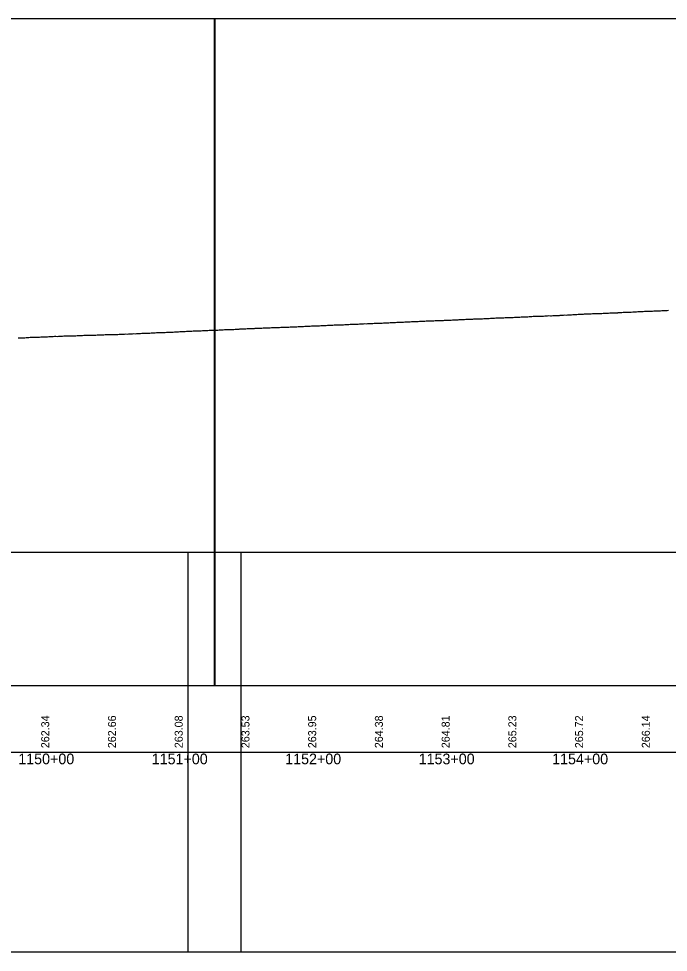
# Model space of a CAD drawing. Extents: x -3627 to 47473, y 2850 to 4350.
# Drawn here: x 2353 to 2840, y 2850 to 3550 of the extents above; entities that cross this region are included whole.
import ezdxf

# ---------------------------------------------------------------- set-up
doc = ezdxf.new("R2010")
doc.units = 0
for name, color, linetype in [('RD_DDB_Profile_EX', 7, 'Continuous'), ('RD_DDB_StaTX', 7, 'Continuous'), ('RD_DDB_StripGrade', 7, 'Continuous'), ('RD_GPK_Profile_Cell', 7, 'Continuous'), ('RD_SHT_ShtClip', 7, 'Continuous')]:
    doc.layers.add(name, color=color, linetype=linetype)

msp = doc.modelspace()

# ---------------------------------------------------------------- linework, layer by layer
at = {"layer": 'RD_DDB_Profile_EX'}
for points in [[(2633.790512, 3322.19143), (2634.793916, 3322.19946), (2635.790637, 3322.29861), (2636.793829, 3322.34696), (2637.783841, 3322.395415), (2638.787037, 3322.49412), (2639.124858, 3322.512035), (2639.79033, 3322.54469), (2640.787584, 3322.505735), (2641.790926, 3322.508085), (2642.788456, 3322.60648), (2643.791934, 3322.60825), (2644.781844, 3322.66005), (2645.785627, 3322.71375), (2646.394238, 3322.77472), (2646.782753, 3322.81139), (2647.78638, 3322.86255), (2648.790306, 3322.86363), (2650.028928, 3322.983285), (2650.791259, 3323.055685), (2651.781736, 3323.056225), (2652.785513, 3323.060725), (2653.782887, 3323.111245), (2654.787109, 3323.2091), (2655.78656, 3323.15732), (2656.750391, 3323.20531), (2657.298309, 3323.26141), (2657.787457, 3323.309415), (2658.785119, 3323.354915), (2659.78944, 3323.402415), (2660.932999, 3323.39969), (2661.749978, 3323.40096), (2662.537004, 3323.453005), (2663.541312, 3323.45581), (2664.567689, 3323.507625), (2665.528994, 3323.60698), (2666.53333, 3323.60918), (2667.530566, 3323.70545), (2668.534916, 3323.65942), (2669.532193, 3323.661045), (2670.529467, 3323.806715), (2671.533843, 3323.808315), (2671.837069, 3323.823375), (2672.53115, 3323.85755), (2673.535298, 3323.95841), (2674.532888, 3323.961215), (2675.530485, 3324.010165), (2676.534404, 3324.0585), (2677.532046, 3324.056825), (2678.536236, 3324.10506), (2679.106449, 3324.161215), (2679.533624, 3324.201185), (2680.531326, 3324.200825), (2681.535561, 3324.19834), (2682.741139, 3324.30623), (2683.537545, 3324.34514), (2684.535018, 3324.437805), (2685.532795, 3324.48469), (2686.537385, 3324.485665), (2687.534615, 3324.531935), (2688.539255, 3324.62796), (2689.536789, 3324.67408), (2690.010519, 3324.67224), (2690.534361, 3324.672385), (2691.539068, 3324.719975), (2692.536669, 3324.763055), (2693.645209, 3324.77055), (2694.539044, 3324.855675), (2695.536715, 3324.90045), (2696.561209, 3324.9003), (2697.559781, 3324.98992), (2698.564217, 3325.033595), (2699.562895, 3325.027935), (2700.503658, 3325.022265), (2700.948067, 3325.03156), (2701.939405, 3325.132825), (2702.944497, 3325.23141), (2703.949212, 3325.233025), (2704.549279, 3325.20557), (2704.940935, 3325.19241), (2705.945371, 3325.20102), (2706.937117, 3325.349485), (2708.183969, 3325.40145), (2708.946822, 3325.405865), (2709.938619, 3325.503985), (2710.943539, 3325.604555), (2711.935321, 3325.609905), (2712.940008, 3325.61436), (2713.938649, 3325.666495), (2714.936878, 3325.716635), (2715.45335, 3325.74353), (2715.941954, 3325.768325), (2716.933874, 3325.817755), (2717.939007, 3325.8671), (2719.08804, 3325.870875), (2719.935826, 3325.871815), (2720.941373, 3325.924695), (2721.933068, 3325.97144), (2722.938637, 3326.02415), (2723.937248, 3326.07643), (2724.935785, 3326.12437)], [(2724.935785, 3326.12437), (2725.941438, 3326.17435), (2726.35742, 3326.15356), (2726.932996, 3326.128455), (2727.938762, 3326.17986), (2728.937489, 3326.327285), (2729.99211, 3326.374975), (2730.94201, 3326.42285), (2731.934044, 3326.46953), (2732.93993, 3326.46801), (2733.911784, 3326.4693), (2734.917295, 3326.567595), (2735.923136, 3326.66145), (2736.914845, 3326.66012), (2737.26149, 3326.69387), (2737.920377, 3326.755585), (2738.912475, 3326.85127), (2739.918018, 3326.85112), (2740.923555, 3326.84862), (2741.915716, 3326.893505), (2742.739913, 3326.89674), (2743.739141, 3326.903055), (2744.739051, 3326.956795), (2745.73869, 3327.009845), (2746.744588, 3327.06056), (2747.74456, 3327.159265), (2748.16556, 3327.15962), (2748.737001, 3327.15988), (2749.736737, 3327.260045), (2750.736786, 3327.36037), (2751.80025, 3327.31729), (2752.736051, 3327.32088), (2753.735899, 3327.370565), (2754.735732, 3327.42215), (2755.735312, 3327.471565), (2756.735545, 3327.52249), (2757.735101, 3327.56859), (2758.734749, 3327.57368), (2759.06963, 3327.5907), (2759.735056, 3327.624085), (2760.734813, 3327.720125), (2761.734854, 3327.816055), (2762.735199, 3327.864125), (2763.735066, 3327.81766), (2764.735218, 3327.86903), (2765.735386, 3327.96228), (2766.33901, 3327.990815), (2766.729231, 3328.011325), (2767.736115, 3328.05961), (2768.736404, 3328.10617), (2769.973701, 3328.176045), (2770.736773, 3328.24652), (2771.737183, 3328.296645), (2772.737594, 3328.34456), (2773.738021, 3328.394665), (2774.738559, 3328.44183), (2775.732168, 3328.532085), (2776.684649, 3328.57671), (2777.368549, 3328.58376), (2778.369765, 3328.63029), (2779.364795, 3328.636535), (2780.373275, 3328.687745), (2780.877771, 3328.740535), (2781.368307, 3328.78908), (2782.363056, 3328.79676), (2783.371576, 3328.895115), (2784.512461, 3328.9432), (2785.367865, 3328.902265), (2786.370208, 3328.906845), (2787.364985, 3328.963385), (2788.366255, 3329.01282), (2789.368632, 3329.0645), (2790.369926, 3329.06533), (2791.364997, 3329.16682), (2791.781841, 3329.21003), (2792.367135, 3329.26622), (2793.368465, 3329.264195), (2794.363568, 3329.314915), (2795.416531, 3329.319395), (2796.367351, 3329.36708), (2797.362495, 3329.465005), (2798.37092, 3329.468515), (2799.366079, 3329.470175), (2800.367498, 3329.51256), (2801.362695, 3329.513715), (2802.365193, 3329.567065), (2802.685911, 3329.597955), (2803.366382, 3329.66102), (2804.361636, 3329.661435), (2805.3704, 3329.75503), (2806.365661, 3329.85115), (2807.360983, 3329.898615), (2808.36951, 3329.897865), (2809.364835, 3329.89758), (2809.955291, 3329.95347), (2810.36639, 3329.99205), (2811.369052, 3330.04324), (2812.364455, 3330.04232), (2813.589981, 3330.174735), (2814.375418, 3330.323265), (2815.377009, 3330.319135)], [(2815.377009, 3330.319135), (2816.372724, 3330.31548), (2817.375286, 3330.364065), (2818.376953, 3330.40676), (2819.372783, 3330.44968), (2820.381987, 3330.44738), (2820.859361, 3330.493035), (2821.377107, 3330.542605), (2822.373061, 3330.63178), (2823.229437, 3330.637815), (2824.494051, 3330.656145), (2825.230309, 3330.693765), (2826.227656, 3330.700155), (2827.23172, 3330.703885), (2828.229476, 3330.76019), (2829.226609, 3330.910545), (2830.230809, 3330.913385), (2831.228678, 3330.916315), (2831.763432, 3330.94477), (2832.226226, 3330.966225), (2833.230227, 3331.06326), (2834.221138, 3331.06584), (2835.398122, 3331.17672), (2836.223222, 3331.2192), (2837.221029, 3331.22322), (2838.218797, 3331.179465), (2839.223316, 3331.22548), (2840.221611, 3331.36848)], [(2451.684694, 3314.29795), (2452.681468, 3314.34704), (2453.755665, 3314.40245), (2454.672582, 3314.44725), (2455.675191, 3314.547285), (2456.67779, 3314.597385), (2457.674714, 3314.64586), (2458.675539, 3314.695455), (2459.180865, 3314.745955), (2460.183572, 3314.79573), (2461.178315, 3314.79662), (2462.179176, 3314.79853), (2463.181943, 3314.79781), (2464.176745, 3314.898195), (2464.659735, 3314.923285), (2465.177642, 3314.949965), (2466.180482, 3315.048785), (2467.476991, 3315.085265), (2468.294425, 3315.043655), (2469.17921, 3314.99894), (2470.180222, 3315.19998), (2471.183143, 3315.198335), (2472.17812, 3315.247845), (2473.179224, 3315.29857), (2474.182225, 3315.346485), (2475.177279, 3315.395665), (2475.563805, 3315.395945), (2476.178422, 3315.3962), (2477.181518, 3315.393855), (2478.176648, 3315.492185), (2479.198495, 3315.640985), (2480.181026, 3315.63946), (2481.182316, 3315.58972), (2482.18551, 3315.686535), (2482.833185, 3315.717975), (2483.180769, 3315.735005), (2484.182164, 3315.883435), (2485.185445, 3315.880695), (2486.467876, 3315.85793), (2487.182242, 3315.92809), (2488.185643, 3315.97378), (2489.181073, 3315.971215), (2490.190464, 3316.0682), (2491.186079, 3316.115155), (2492.175247, 3316.162135), (2493.184193, 3316.209385), (2493.737256, 3316.26327), (2494.179308, 3316.30446), (2495.174456, 3316.301855), (2496.183562, 3316.34759), (2497.371946, 3316.392595), (2498.179977, 3316.39171), (2499.182757, 3316.485195), (2500.177979, 3316.53117), (2501.006636, 3316.534105), (2501.721192, 3316.5354), (2502.721232, 3316.5367), (2503.721273, 3316.58673), (2504.721324, 3316.6842), (2505.7215, 3316.781225), (2506.719763, 3316.83378), (2507.71979, 3316.88453), (2508.276016, 3316.88429), (2508.720028, 3316.885135), (2509.720546, 3316.88548), (2510.720864, 3316.93461), (2511.910706, 3317.0027), (2512.727499, 3317.08143), (2513.720169, 3317.082715), (2514.720635, 3317.082685), (2515.721127, 3317.178585), (2516.721744, 3317.27674), (2517.72219, 3317.273425), (2518.722803, 3317.32154), (2519.180086, 3317.34415), (2519.729364, 3317.370995), (2520.722365, 3317.37003), (2521.723135, 3317.41919), (2522.814776, 3317.475665), (2523.725081, 3317.560825), (2524.72602, 3317.60792), (2525.732789, 3317.610035), (2526.733769, 3317.607105), (2527.726931, 3317.70157), (2528.728031, 3317.74632), (2529.729132, 3317.79477), (2530.084156, 3317.8113), (2530.730344, 3317.843035), (2531.731615, 3317.887165), (2532.727277, 3317.887215), (2533.728085, 3317.88353), (2534.721429, 3317.9287), (2535.722287, 3318.022345), (2536.723505, 3318.11579), (2537.353536, 3318.112955), (2537.724101, 3318.113765), (2538.731359, 3318.113185), (2539.93407, 3318.15564), (2540.988226, 3318.1662), (2541.936477, 3318.259605), (2542.934592, 3318.35792)], [(2542.934592, 3318.35792), (2543.938671, 3318.360525), (2544.929381, 3318.41041), (2545.9279, 3318.41562), (2546.931784, 3318.46525), (2547.930297, 3318.51566), (2548.257607, 3318.51582), (2548.928515, 3318.51816), (2549.933176, 3318.61501), (2550.931133, 3318.66491), (2551.935444, 3318.714225), (2552.934165, 3318.763605), (2553.93253, 3318.81306), (2554.937303, 3318.81643), (2555.526987, 3318.816115), (2555.935422, 3318.815605), (2556.934262, 3318.871485), (2557.931403, 3318.9189), (2559.161677, 3318.97691), (2559.928526, 3319.01394), (2560.933176, 3319.014025), (2561.932144, 3319.01475), (2562.930766, 3319.115535), (2563.935909, 3319.11504), (2564.934332, 3319.210485), (2565.93306, 3319.258425), (2566.431057, 3319.28303), (2566.938271, 3319.30516), (2567.937131, 3319.35254), (2568.936065, 3319.39975), (2570.065747, 3319.413855), (2570.932981, 3319.49188), (2571.931989, 3319.538625), (2572.937414, 3319.59242), (2573.910466, 3319.63673), (2574.908926, 3319.68339), (2575.914055, 3319.728775), (2576.91251, 3319.77249), (2577.335127, 3319.77087), (2577.911389, 3319.76887), (2578.916131, 3319.819635), (2579.914635, 3319.862705), (2580.969817, 3319.962785), (2581.744461, 3320.058355), (2582.741745, 3320.01343), (2583.744685, 3320.06121), (2584.741517, 3320.11329), (2585.738822, 3320.120875), (2586.741882, 3320.126995), (2587.738804, 3320.175665), (2588.239197, 3320.251735), (2588.736211, 3320.321175), (2589.740778, 3320.37067), (2590.743959, 3320.37626), (2591.873887, 3320.43021), (2592.738117, 3320.43062), (2593.741783, 3320.480135), (2594.738926, 3320.480615), (2595.73651, 3320.53088), (2596.733772, 3320.53354), (2597.7372, 3320.632455), (2598.742002, 3320.772665), (2599.143268, 3320.7324), (2599.739336, 3320.68319), (2600.73672, 3320.72984), (2601.740687, 3320.87538), (2602.777958, 3320.883505), (2603.735937, 3321.02091), (2604.739614, 3321.02148), (2605.737126, 3321.023025), (2606.735044, 3321.024525), (2607.732692, 3321.069975), (2608.744097, 3321.120995), (2609.741741, 3321.169255), (2610.047338, 3321.16872), (2610.73986, 3321.170135), (2611.743789, 3321.266655), (2612.741571, 3321.35846), (2613.739361, 3321.312025), (2614.726502, 3321.359465), (2615.730387, 3321.44965), (2616.728036, 3321.49713), (2617.316718, 3321.4943), (2617.733226, 3321.492525), (2618.737201, 3321.544385), (2619.734948, 3321.588155), (2620.951408, 3321.597845), (2621.806675, 3321.60518), (2622.803027, 3321.65844), (2623.806501, 3321.75759), (2624.795838, 3321.76259), (2625.798595, 3321.819925), (2626.795455, 3321.875305), (2627.798226, 3321.8824), (2628.220788, 3321.925935), (2628.795135, 3321.97678), (2629.798034, 3322.03078), (2630.800949, 3322.03478), (2631.855478, 3322.092965), (2632.793828, 3322.18977), (2633.790512, 3322.19143)], [(2352.929829, 3310.73245), (2353.932394, 3310.733485), (2354.927051, 3310.83385), (2355.929615, 3310.83485), (2356.926078, 3310.834785), (2357.928642, 3310.835755), (2358.931152, 3310.93579), (2359.925859, 3310.93712), (2360.928376, 3310.98723), (2361.930941, 3311.087755), (2362.927403, 3311.087605), (2363.922099, 3311.088935), (2364.924622, 3311.139435), (2365.927187, 3311.14026), (2366.929763, 3311.19074), (2367.932327, 3311.240955), (2368.920908, 3311.29125), (2369.923469, 3311.44099), (2370.926002, 3311.49106), (2371.928565, 3311.442325), (2372.933068, 3311.44308), (2373.927318, 3311.494295), (2374.923934, 3311.54355), (2375.92635, 3311.59411), (2376.928766, 3311.644665), (2377.923035, 3311.74602), (2379.17513, 3311.79553), (2380.177626, 3311.845865), (2381.174174, 3311.84513), (2382.176655, 3311.795955), (2383.173183, 3311.84524), (2384.175679, 3311.89572), (2385.172227, 3311.945225), (2386.174722, 3311.995815), (2387.171272, 3312.094825), (2388.173733, 3312.09546), (2389.17028, 3312.095065), (2390.172776, 3312.19544), (2391.169325, 3312.24479), (2392.171819, 3312.245655), (2393.168349, 3312.1953), (2394.170829, 3312.24587), (2395.167378, 3312.29502), (2396.169872, 3312.29562), (2397.180365, 3312.34525), (2398.176912, 3312.44449), (2399.17941, 3312.44511), (2400.175958, 3312.444615), (2401.178439, 3312.445465), (2402.174964, 3312.5946), (2403.177463, 3312.5952), (2404.174011, 3312.644445), (2405.176507, 3312.64506), (2406.173057, 3312.64443), (2407.175516, 3312.64517), (2408.172063, 3312.744555), (2409.17456, 3312.745025), (2410.171109, 3312.694685), (2411.173584, 3312.79514), (2412.170133, 3312.89424), (2413.172135, 3312.895), (2414.168607, 3312.944365), (2415.171163, 3313.04472), (2416.167652, 3313.044205), (2417.178123, 3313.043815), (2418.174593, 3313.093165), (2419.17715, 3313.09395), (2420.173641, 3313.14332), (2420.679405, 3313.1444), (2421.681791, 3313.19473), (2422.678438, 3313.194085), (2423.680838, 3313.194845), (2424.683239, 3313.24546), (2425.67987, 3313.294695), (2426.682271, 3313.295325), (2427.678896, 3313.294815), (2428.681284, 3313.395305), (2429.683687, 3313.495935), (2430.68033, 3313.49529), (2431.682731, 3313.44592), (2432.679362, 3313.54527), (2433.681763, 3313.596), (2434.684165, 3313.546615), (2435.68079, 3313.595885), (2436.683182, 3313.69651), (2437.679822, 3313.745865), (2438.682225, 3313.79649), (2439.678866, 3313.84564), (2440.681257, 3313.796385), (2441.683659, 3313.8471), (2442.680284, 3313.896455), (2443.682687, 3313.947155), (2444.679316, 3313.99644), (2445.681719, 3314.146845), (2446.684122, 3314.19752), (2447.68076, 3314.146975), (2448.683154, 3314.147615), (2449.679792, 3314.196955), (2450.120975, 3314.197235), (2450.682222, 3314.197555), (2451.684694, 3314.29795)]]:
    msp.add_lwpolyline(points, dxfattribs=at)
at = {"layer": 'RD_GPK_Profile_Cell'}
msp.add_line((1000, 3000), (46705.077602, 3000), dxfattribs=at)
at = {"layer": 'RD_SHT_ShtClip'}
for points in [[(2500.165, 3050), (2500.165, 3550), (2500.165, 3550), (1000.33, 3550), (1000.33, 3050)], [(4000.165, 3050), (4000.165, 3550), (4000.165, 3550), (2500.33, 3550), (2500.33, 3050)], [(980.33, 3150), (2520, 3150), (2520, 2850), (980.33, 2850)], [(2480.33, 3150), (4020, 3150), (4020, 2850), (2480.33, 2850)]]:
    msp.add_lwpolyline(points, close=True, dxfattribs=at)

# ---------------------------------------------------------------- texts
at = {"layer": 'RD_DDB_StaTX'}
for s, p in [('1150+00', (2353.125471, 2991)), ('1151+00', (2453.125471, 2991)), ('1152+00', (2553.125471, 2991)), ('1153+00', (2653.125471, 2991)), ('1154+00', (2753.125471, 2991))]:
    msp.add_text(s, height=8, dxfattribs=at).set_placement(p)
at = {"layer": 'RD_DDB_StripGrade'}
for s, p in [('262.34', (2376.33, 3003.073688)), ('262.66', (2426.33, 3003.073688)), ('263.08', (2476.33, 3003.073688)), ('263.53', (2526.33, 3003.073688)), ('263.95', (2576.33, 3003.073688)), ('264.38', (2626.33, 3003.073688)), ('264.81', (2676.33, 3003.073688)), ('265.23', (2726.33, 3003.073688)), ('265.72', (2776.33, 3003.073688)), ('266.14', (2826.33, 3003.073688))]:
    msp.add_text(s, height=6, rotation=90, dxfattribs=at).set_placement(p)

doc.saveas('drawing.dxf')
